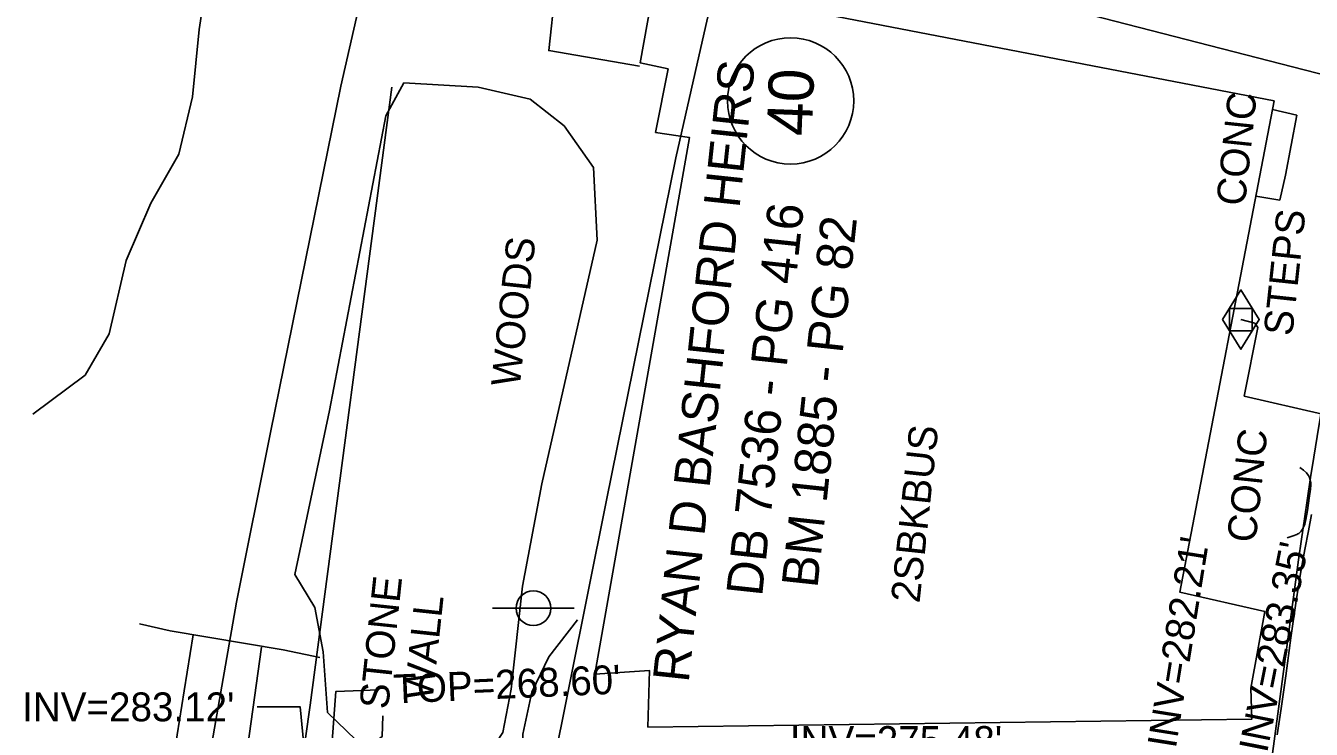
# Model space of a CAD drawing. Extents: x 2100323 to 2109811, y 740376 to 749755.
# Drawn here: x 2105015.8 to 2105194, y 742196.2 to 742293.7 of the extents above; entities that cross this region are included whole.
import ezdxf

# ---------------------------------------------------------------- set-up
doc = ezdxf.new("R2010")
doc.units = 0
for name, color, linetype in [('Exist Building', 7, 'Continuous'), ('Exist Building Leader', 7, 'Continuous'), ('Exist Building Text', 7, 'Continuous'), ('Exist Other Culture Area Outline', 7, 'Continuous'), ('Exist Other Culture Area Outline Text', 7, 'Continuous'), ('Exist Property Deed Book Text', 7, 'Continuous'), ('Exist Property Line', 7, 'Continuous'), ('Exist Property Owner Number CELL', 7, 'Continuous'), ('Exist Property Owner Text', 7, 'Continuous'), ('Exist Railroads Standard Gauge', 7, 'Continuous'), ('Exist Right of Way Line', 7, 'Continuous'), ('Exist Roads Curbs', 7, 'Continuous'), ('Exist Roads Curbs Text', 7, 'Continuous'), ('Exist Roads EOP', 7, 'Continuous'), ('Exist Roads EOP Other', 7, 'Continuous'), ('Exist Structure Major Bridge WW', 7, 'Continuous'), ('Exist Structure Major Deck Tunnel Box Culvert', 7, 'Continuous'), ('Exist Structure Minor Catch Basin Top Elevation', 7, 'Continuous'), ('Exist Structure Minor Pipes RCP 15 Inch Invert', 7, 'Continuous'), ('Exist Structure Minor Pipes RCP 15 Inch Leader', 7, 'Continuous'), ('Exist Utilities Gas Meter CELL', 7, 'Continuous'), ('Exist Utilities Gas UG Line SUE LOS B', 7, 'Continuous'), ('Exist Utilities Sanitary Sewer UG Line Invert Elevation', 7, 'Continuous'), ('Exist Utilities Telephone Pole CELL', 7, 'Continuous'), ('Exist Utilities Telephone UG FO SUE LOS C', 7, 'Continuous'), ('Exist Vegetation Woods Line', 7, 'Continuous'), ('Exist Vegetation Woods Line Text', 7, 'Continuous')]:
    doc.layers.add(name, color=color, linetype=linetype)

msp = doc.modelspace()

# ---------------------------------------------------------------- linework, layer by layer
at = {"layer": 'Exist Building'}
msp.add_lwpolyline([(2105100.89, 742288.11), (2105088.32, 742290.28), (2105089.2, 742298.49), (2105089.94, 742304.14), (2105090.65, 742307.91), (2105091.57, 742311.97)], dxfattribs=at)
msp.add_lwpolyline([(2105188.86, 742283.3), (2105175.79, 742215.21), (2105187.56, 742212.53), (2105185.64, 742201.94), (2105185.75, 742197.61), (2105102.06, 742196.52), (2105102.26, 742204.38), (2105094.69, 742203.84), (2105107.84, 742278.23), (2105103.12, 742278.95), (2105104.86, 742287.74), (2105100.98, 742288.59), (2105103.04, 742299.9)], close=True, dxfattribs=at)
at = {"layer": 'Exist Building Leader'}
msp.add_lwpolyline([(2105055.79, 742188.1), (2105065.21, 742195.22), (2105065.31, 742198.08)], dxfattribs=at)
at = {"layer": 'Exist Other Culture Area Outline'}
msp.add_lwpolyline([(2105188.62, 742282.1), (2105191.99, 742281.33), (2105190.43, 742273.03), (2105189.64, 742269.56), (2105186.32, 742270.09)], dxfattribs=at)
at = {"layer": 'Exist Property Line'}
msp.add_line((2105204.63, 742284.62), (2105113.39, 742308.13), dxfattribs=at)
at = {"layer": 'Exist Property Owner Number CELL'}
msp.add_circle((2105121.83, 742283.31), 8.75, dxfattribs=at)
at = {"layer": 'Exist Railroads Standard Gauge'}
msp.add_lwpolyline([(2105033.66, 742143.07), (2105036.96, 742166.51), (2105041.49, 742193.45), (2105045.04, 742213.86), (2105049.76, 742237.36), (2105059.5, 742285.36), (2105063.08, 742301.18), (2105065.78, 742313.18)], dxfattribs=at)
at = {"layer": 'Exist Right of Way Line'}
msp.add_line((2105188.22, 742190.04), (2105192.25, 742219.7), dxfattribs=at)
msp.add_lwpolyline([(2105088.65, 742189.77), (2105096.32, 742227.96), (2105105.95, 742275.4), (2105109.41, 742290.73), (2105112.12, 742302.74)], dxfattribs=at)
msp.add_arc((2105806.6, 742136.18), 620, 163.74424, 172.25768, dxfattribs=at)
at = {"layer": 'Exist Roads Curbs'}
msp.add_lwpolyline([(2105190.66, 742222.77), (2105191.48, 742223.03), (2105192.01, 742223.22), (2105192.16, 742223.3), (2105192.27, 742223.37), (2105192.38, 742223.46), (2105192.59, 742223.69), (2105192.79, 742223.98), (2105192.97, 742224.31), (2105193.1, 742224.65), (2105193.25, 742225.31), (2105193.46, 742226.56), (2105193.72, 742228.24), (2105193.89, 742229.48), (2105193.96, 742230.11), (2105193.94, 742230.44), (2105193.87, 742230.78), (2105193.74, 742231.11), (2105193.6, 742231.4), (2105193.44, 742231.64), (2105193.32, 742231.77), (2105192.91, 742232.12), (2105192.41, 742232.48)], dxfattribs=at)
at = {"layer": 'Exist Roads EOP'}
msp.add_lwpolyline([(2105194.03, 742225.97), (2105193.62, 742223.74), (2105193.13, 742221.14), (2105192.56, 742218.07), (2105191.91, 742214.02), (2105191.19, 742208.89), (2105190.47, 742203.62), (2105189.84, 742199.12), (2105189.29, 742195.45)], dxfattribs=at)
at = {"layer": 'Exist Roads EOP Other'}
msp.add_lwpolyline([(2105045.28, 742184.51), (2105049.29, 742184.81), (2105071.61, 742186.64), (2105082.2, 742187.23), (2105084.24, 742187.46), (2105084.58, 742188.72), (2105084.72, 742195.57), (2105085.99, 742201.38), (2105088.31, 742206.27), (2105092.28, 742211.37)], dxfattribs=at)
at = {"layer": 'Exist Structure Major Bridge WW'}
msp.add_lwpolyline([(2105056.59, 742206.16), (2105051.5, 742207.25), (2105035.86, 742209.86), (2105031.61, 742210.86)], dxfattribs=at)
at = {"layer": 'Exist Structure Major Deck Tunnel Box Culvert'}
for points in [[(2105022.96, 742094.51), (2105026.09, 742117.87), (2105029.09, 742143.41), (2105032.15, 742163.32), (2105034.86, 742183.27), (2105037.77, 742201.55), (2105039.05, 742209.31)], [(2105048.5, 742207.62), (2105043.46, 742171.41), (2105038.34, 742136.04), (2105035.14, 742112.22), (2105033.02, 742093.25)]]:
    msp.add_lwpolyline(points, dxfattribs=at)
at = {"layer": 'Exist Structure Minor Catch Basin Top Elevation'}
msp.add_lwpolyline([(2105056.9, 742175.81), (2105058.79, 742201.45), (2105064.78, 742201.71)], dxfattribs=at)
at = {"layer": 'Exist Structure Minor Pipes RCP 15 Inch Leader'}
msp.add_lwpolyline([(2105056.12, 742175.86), (2105053.88, 742199.33), (2105047.88, 742199.33)], dxfattribs=at)
at = {"layer": 'Exist Utilities Gas Meter CELL'}
msp.add_line((2105184.24, 742253.01), (2105184.24, 742253.01), dxfattribs=at)
for points in [[(2105181.7, 742253.01), (2105184.24, 742257.12), (2105186.78, 742253.01), (2105184.24, 742248.9), (2105181.7, 742253.01)], [(2105182.66, 742254.55), (2105185.81, 742254.55), (2105185.81, 742251.43), (2105182.66, 742251.43), (2105182.66, 742254.55)]]:
    msp.add_lwpolyline(points, dxfattribs=at)
at = {"layer": 'Exist Utilities Gas UG Line SUE LOS B'}
msp.add_line((2105186.18, 742252.51), (2105184.24, 742253.01), dxfattribs=at)
msp.add_lwpolyline([(2105222.57, 742234.92), (2105208.53, 742238.27), (2105195.56, 742239.91), (2105184.7, 742242.4), (2105186.61, 742251.89), (2105186.18, 742252.51)], dxfattribs=at)
at = {"layer": 'Exist Utilities Telephone Pole CELL'}
for p, q in [((2105080.51, 742213), (2105091.85, 742213)), ((2105086.19, 742213), (2105086.19, 742213))]:
    msp.add_line(p, q, dxfattribs=at)
msp.add_circle((2105086.19, 742213), 2.41, dxfattribs=at)
at = {"layer": 'Exist Utilities Telephone UG FO SUE LOS C'}
msp.add_lwpolyline([(2105039.04, 742084.87), (2105055.27, 742199.57), (2105066.58, 742285.22)], dxfattribs=at)
at = {"layer": 'Exist Vegetation Woods Line'}
for points in [[(2105047.47, 742312.62), (2105041.04, 742300.82), (2105039.86, 742293.21), (2105038.92, 742283.87), (2105037.04, 742275.93), (2105033.16, 742269.13), (2105029.74, 742261.18), (2105027.39, 742251.03), (2105024.05, 742245.31), (2105016.83, 742239.9)], [(2105068.23, 742285.82), (2105078.55, 742285.21), (2105085.75, 742283.55), (2105090.46, 742279.84), (2105094.51, 742274.08), (2105095.01, 742264.03), (2105087.37, 742230.25), (2105084.68, 742216.08), (2105083.1, 742201.8), (2105081.97, 742195.79), (2105078.63, 742190.68), (2105071.59, 742190.31), (2105064.23, 742192.22), (2105057.63, 742198.57), (2105057.04, 742206.97), (2105055.91, 742213.11), (2105053.11, 742217.66), (2105057.91, 742240.41), (2105065.75, 742281.23), (2105068.23, 742285.82)]]:
    msp.add_lwpolyline(points, dxfattribs=at)

# ---------------------------------------------------------------- texts
at = {"layer": 'Exist Building Text'}
for s, rotation, p in [('2SBKBUS', 83.8849, (2105139.7, 742213.63)), ('STONE', 83.8864, (2105066.04, 742198.9)), ('WALL', 83.8864, (2105072.2, 742200.12))]:
    msp.add_text(s, height=4, rotation=rotation, dxfattribs=at).set_placement(p)
at = {"layer": 'Exist Other Culture Area Outline Text'}
msp.add_text('STEPS', height=4, rotation=83.8864, dxfattribs=at).set_placement((2105191.36, 742250.63))
at = {"layer": 'Exist Property Deed Book Text'}
for s, p in [('DB 7536 - PG 416', (2105117.88, 742214.54)), ('BM 1885 - PG 82', (2105125.55, 742215.7))]:
    msp.add_text(s, height=5, rotation=83.8864, dxfattribs=at).set_placement(p)
at = {"layer": 'Exist Property Owner Number CELL'}
msp.add_text('40', height=6.25, rotation=87.7944, dxfattribs=at).set_placement((2105124.76, 742278.37))
at = {"layer": 'Exist Property Owner Text'}
msp.add_text('RYAN D BASHFORD HEIRS', height=5, rotation=83.8874, dxfattribs=at).set_placement((2105107.7, 742202.6))
at = {"layer": 'Exist Roads Curbs Text'}
for p in [(2105184.79, 742268.64), (2105186.28, 742221.98)]:
    msp.add_text('CONC', height=4, rotation=83.8864, dxfattribs=at).set_placement(p)
at = {"layer": 'Exist Structure Minor Catch Basin Top Elevation'}
msp.add_text("TOP=268.60'", height=4, rotation=2.5074, dxfattribs=at).set_placement((2105066.87, 742199.8))
at = {"layer": 'Exist Structure Minor Pipes RCP 15 Inch Invert'}
for s, p in [("INV=283.12'", (2105015.33, 742197.33)), ("INV=275.48'", (2105121.74, 742192.66))]:
    msp.add_text(s, height=4, dxfattribs=at).set_placement(p)
at = {"layer": 'Exist Utilities Sanitary Sewer UG Line Invert Elevation'}
for s, rotation, p in [("INV=282.21'", 80.9154, (2105175.22, 742193.46)), ("INV=283.35'", 78.6971, (2105187.87, 742192.83))]:
    msp.add_text(s, height=4, rotation=rotation, dxfattribs=at).set_placement(p)
at = {"layer": 'Exist Vegetation Woods Line Text'}
msp.add_text('WOODS', height=4, rotation=83.8864, dxfattribs=at).set_placement((2105084.29, 742243.56))

doc.saveas('drawing.dxf')
